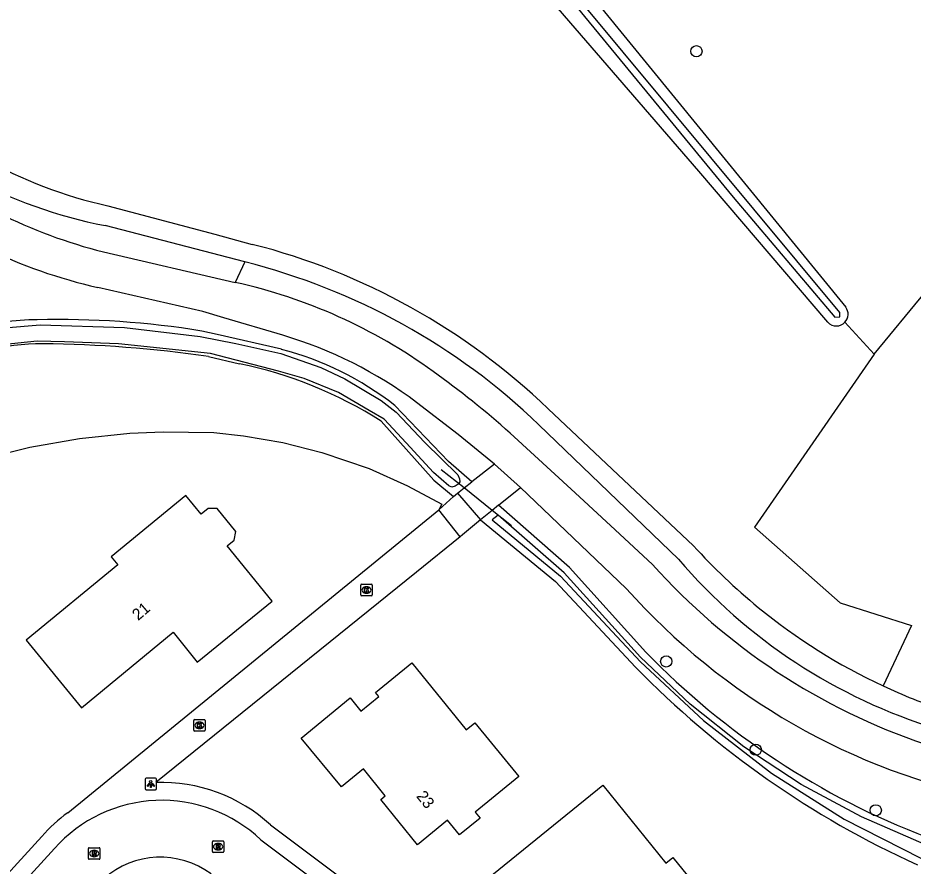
# Model space of a CAD drawing. Extents: x 159628 to 160723, y 388176 to 389416.
# Drawn here: x 160106.4 to 160184.1, y 388841.4 to 388915 of the extents above; entities that cross this region are included whole.
import ezdxf

# ---------------------------------------------------------------- set-up
doc = ezdxf.new("R2010")
doc.units = 0
for name, color, linetype in [('IMGEO_Berm_groen', 7, 'Continuous'), ('IMGEO_Boom', 7, 'Continuous'), ('IMGEO_Duiker', 7, 'Continuous'), ('IMGEO_Erf', 7, 'Continuous'), ('IMGEO_Fietspad_gesloten', 7, 'Continuous'), ('IMGEO_Grasland_agrarisch', 7, 'Continuous'), ('IMGEO_Grasland_overig', 7, 'Continuous'), ('IMGEO_Kolk', 7, 'Continuous'), ('IMGEO_Lichtpunt', 7, 'Continuous'), ('IMGEO_Loofbos', 7, 'Continuous'), ('IMGEO_Muur', 7, 'Continuous'), ('IMGEO_Pand', 7, 'Continuous'), ('IMGEO_Pand_nummerreeks', 7, 'Continuous'), ('IMGEO_Rijbaan_lokaal_open', 7, 'Continuous'), ('IMGEO_Rioolput', 7, 'Continuous'), ('IMGEO_Voetpad_open', 7, 'Continuous'), ('IMGEO_Waterloop', 7, 'Continuous')]:
    doc.layers.add(name, color=color, linetype=linetype)

msp = doc.modelspace()

# ---------------------------------------------------------------- linework, layer by layer
at = {"layer": 'IMGEO_Berm_groen'}
for points in [[(160126.079, 388893.808), (160125.223, 388892.036)], [(160160.876, 388859.965), (160154.236, 388867.293), (160148.075, 388872.699)]]:
    msp.add_lwpolyline(points, dxfattribs=at)
msp.add_arc((160209.329, 388907.014), 67.537, 224.15722, 249.1234, dxfattribs=at)
at = {"layer": 'IMGEO_Boom'}
for centre in [(160165.267, 388912.086), (160162.647, 388859.156), (160170.41, 388851.499), (160180.828, 388846.239)]:
    msp.add_circle(centre, 0.489, dxfattribs=at)
at = {"layer": 'IMGEO_Duiker'}
msp.add_lwpolyline([(160149.214, 388870.917), (160147.533, 388872.261), (160145.099, 388874.206), (160143.12, 388875.788)], dxfattribs=at)
at = {"layer": 'IMGEO_Erf'}
msp.add_lwpolyline([(160146.523, 388871.443), (160153.027, 388866.078), (160159.969, 388858.667)], dxfattribs=at)
msp.add_arc((160217.806, 388915.151), 80.842, 224.32195, 245.63246, dxfattribs=at)
at = {"layer": 'IMGEO_Fietspad_gesloten'}
for points in [[(160113.801, 388894.677), (160125.223, 388892.036)], [(160129.373, 388887.452), (160124.242, 388888.964), (160122.442, 388889.495), (160113.319, 388891.599)], [(160147.737, 388876.259), (160144.602, 388878.841), (160140.983, 388881.624)], [(160149.101, 388878.958), (160154.74, 388873.784), (160158.211, 388870.565), (160161.453, 388867.574)], [(160149.983, 388874.244), (160147.737, 388876.259)], [(160159.177, 388865.484), (160149.983, 388874.244)]]:
    msp.add_lwpolyline(points, dxfattribs=at)
for centre, radius, start, end in [((160124.753, 388938.066), 44.75, 230.95322, 255.83428), ((160123.158, 388935.319), 44.814, 230.80433, 257.31731), ((160115.19, 388846.727), 46.406, 54.08271, 77.51447), ((160118.674, 388851.661), 37.356, 53.33086, 73.35758), ((160096.478, 388820.054), 78.987, 48.22355, 54.44012), ((160202.862, 388904.655), 55.585, 221.84443, 251.40851), ((160202.564, 388904.147), 58.114, 221.70465, 258.72122)]:
    msp.add_arc(centre, radius, start, end, dxfattribs=at)
at = {"layer": 'IMGEO_Grasland_agrarisch'}
for points in [[(160152.521, 388921.233), (160157.028, 388915.832), (160178.23, 388889.88)], [(160176.67, 388888.573), (160165.48, 388901.685), (160150.482, 388919.031), (160150.332, 388919.393)], [(160178.159, 388888.584), (160180.698, 388885.821)]]:
    msp.add_lwpolyline(points, dxfattribs=at)
for centre, start, end in [((160177.412, 388889.275), 317.23027, 36.49822), ((160177.409, 388889.271), 223.37071, 317.47582)]:
    msp.add_arc(centre, 1.017, start, end, dxfattribs=at)
at = {"layer": 'IMGEO_Grasland_overig'}
for points in [[(160129.253, 388886.228), (160123.678, 388887.511), (160122.355, 388887.816)], [(160145.765, 388874.725), (160143.753, 388876.491), (160139.079, 388881.366)]]:
    msp.add_lwpolyline(points, dxfattribs=at)
for centre, radius, start, end in [((160108.302, 388865.871), 22.924, 90.59566, 105.3732), ((160109.91, 388810.873), 77.943, 80.81269, 91.35748), ((160122.371, 388859.96), 27.154, 52.02728, 75.31942)]:
    msp.add_arc(centre, radius, start, end, dxfattribs=at)
at = {"layer": 'IMGEO_Kolk'}
for p, q in [((160136.131, 388864.922), (160136.131, 388865.774)), ((160136.206, 388865.848), (160137.058, 388865.848)), ((160137.132, 388865.774), (160137.132, 388864.922)), ((160136.642, 388865.068), (160136.617, 388865.068)), ((160136.619, 388865.628), (160136.644, 388865.628)), ((160137.058, 388864.848), (160136.206, 388864.848)), ((160121.637, 388853.186), (160121.637, 388854.038)), ((160121.712, 388854.112), (160122.564, 388854.112)), ((160122.638, 388854.038), (160122.638, 388853.186)), ((160122.148, 388853.332), (160122.123, 388853.332)), ((160122.125, 388853.892), (160122.15, 388853.892)), ((160122.564, 388853.112), (160121.712, 388853.112))]:
    msp.add_line(p, q, dxfattribs=at)
for points in [[(160136.131, 388864.922), (160136.131, 388865.774)], [(160136.206, 388865.848), (160137.058, 388865.848)], [(160137.132, 388865.774), (160137.132, 388864.922)], [(160136.452, 388865.548), (160136.575, 388865.548), (160136.575, 388865.397), (160136.705, 388865.548), (160136.869, 388865.548), (160136.723, 388865.397), (160136.876, 388865.148), (160136.724, 388865.148), (160136.639, 388865.312), (160136.575, 388865.245), (160136.575, 388865.148), (160136.452, 388865.148), (160136.452, 388865.548)], [(160137.058, 388864.848), (160136.206, 388864.848)], [(160121.637, 388853.186), (160121.637, 388854.038)], [(160121.712, 388854.112), (160122.564, 388854.112)], [(160122.638, 388854.038), (160122.638, 388853.186)], [(160121.958, 388853.812), (160122.081, 388853.812), (160122.081, 388853.661), (160122.211, 388853.812), (160122.375, 388853.812), (160122.229, 388853.661), (160122.382, 388853.412), (160122.23, 388853.412), (160122.145, 388853.576), (160122.081, 388853.509), (160122.081, 388853.412), (160121.958, 388853.412), (160121.958, 388853.812)], [(160122.564, 388853.112), (160121.712, 388853.112)]]:
    msp.add_lwpolyline(points, dxfattribs=at)
for centre, start, end in [((160136.208, 388865.772), 91.55205, 178.44795), ((160136.208, 388865.772), 91.55205, 178.44795), ((160137.056, 388865.772), 1.55205, 88.44795), ((160137.056, 388865.772), 1.55205, 88.44795), ((160136.208, 388864.924), 181.55205, 268.44795), ((160136.208, 388864.924), 181.55205, 268.44795), ((160137.056, 388864.924), 271.55205, 358.44795), ((160137.056, 388864.924), 271.55205, 358.44795), ((160121.714, 388854.036), 91.55205, 178.44795), ((160121.714, 388854.036), 91.55205, 178.44795), ((160122.562, 388854.036), 1.55205, 88.44795), ((160122.562, 388854.036), 1.55205, 88.44795), ((160121.714, 388853.188), 181.55205, 268.44795), ((160121.714, 388853.188), 181.55205, 268.44795), ((160122.562, 388853.188), 271.55205, 358.44795), ((160122.562, 388853.188), 271.55205, 358.44795)]:
    msp.add_arc(centre, 0.0765, start, end, dxfattribs=at)
for centre, major_axis, ratio, start_param, end_param in [((160136.618, 388865.348), (-0.387, 0.002), 0.722429, 4.712389, 7.853982), ((160136.643, 388865.348), (-0.39, 0.002), 0.717154, 1.570796, 4.712389), ((160122.124, 388853.612), (-0.387, 0.002), 0.722429, 4.712389, 7.853982), ((160122.149, 388853.612), (-0.39, 0.002), 0.717154, 1.570796, 4.712389)]:
    msp.add_ellipse(centre, major_axis=major_axis, ratio=ratio, start_param=start_param, end_param=end_param, dxfattribs=at)
at = {"layer": 'IMGEO_Lichtpunt'}
for p, q in [((160117.414, 388848.929), (160117.414, 388848.122)), ((160117.414, 388848.929), (160117.414, 388848.122)), ((160118.316, 388849.024), (160117.508, 388849.024)), ((160118.316, 388849.024), (160117.508, 388849.024)), ((160118.41, 388848.122), (160118.41, 388848.929)), ((160118.41, 388848.122), (160118.41, 388848.929)), ((160117.508, 388848.028), (160118.316, 388848.028)), ((160117.508, 388848.028), (160118.316, 388848.028))]:
    msp.add_line(p, q, dxfattribs=at)
for points in [[(160117.788, 388848.593), (160117.827, 388848.565), (160117.639, 388848.303), (160117.601, 388848.33), (160117.788, 388848.593)], [(160118, 388848.565), (160118.038, 388848.592), (160118.225, 388848.33), (160118.186, 388848.302), (160118, 388848.565)], [(160117.89, 388848.545), (160117.937, 388848.545), (160117.937, 388848.223), (160117.89, 388848.223), (160117.89, 388848.545)]]:
    msp.add_lwpolyline(points, dxfattribs=at)
msp.add_circle((160117.913, 388848.727), 0.0994, dxfattribs=at)
for centre, start, end in [((160117.508, 388848.929), 90, 180), ((160117.508, 388848.929), 90, 180), ((160118.316, 388848.929), 0, 90), ((160118.316, 388848.929), 0, 90), ((160117.508, 388848.122), 180, 270), ((160117.508, 388848.122), 180, 270), ((160118.316, 388848.122), 270, 0), ((160118.316, 388848.122), 270, 360)]:
    msp.add_arc(centre, 0.0946, start, end, dxfattribs=at)
at = {"layer": 'IMGEO_Loofbos'}
for points in [[(160180.698, 388885.821), (160198.615, 388907.555), (160207.1, 388917.768)], [(160122.932, 388885.596), (160125.623, 388884.972)], [(160180.698, 388885.821), (160170.293, 388870.81), (160177.732, 388864.231), (160183.942, 388862.28), (160181.458, 388857.036)], [(160137.913, 388879.986), (160142.476, 388874.889), (160144.18, 388873.466)], [(160014.595, 388792.981), (160022.506, 388802.773), (160031.91, 388812.426), (160037.244, 388817.834), (160050.01, 388832.209), (160076.202, 388860.613), (160088.475, 388870.635), (160091.325, 388872.058), (160096.312, 388874.263), (160100.4, 388875.818), (160103.183, 388876.691), (160107.426, 388877.75), (160111.735, 388878.505), (160116.086, 388878.95), (160119, 388879.074), (160123.373, 388879), (160125.963, 388878.728), (160129.384, 388878.138), (160132.751, 388877.291), (160136.853, 388875.88), (160140.197, 388874.392), (160143.174, 388872.785), (160142.904, 388872.292)]]:
    msp.add_lwpolyline(points, dxfattribs=at)
for centre, radius, start, end in [((160108.633, 388865.149), 21.555, 90.2422, 116.86422), ((160107.71, 388781.9), 104.807, 81.64893, 89.54514), ((160118.274, 388849.216), 36.503, 57.45088, 78.38476)]:
    msp.add_arc(centre, radius, start, end, dxfattribs=at)
at = {"layer": 'IMGEO_Muur'}
for points in [[(160144.771, 388869.961), (160140.979, 388866.903)], [(160144.974, 388870.125), (160144.771, 388869.961)], [(160140.979, 388866.903), (160118.345, 388848.647)]]:
    msp.add_lwpolyline(points, dxfattribs=at)
at = {"layer": 'IMGEO_Pand'}
for points in [[(160111.899, 388855.13), (160119.852, 388861.687), (160121.948, 388859.097), (160128.456, 388864.393), (160124.543, 388869.17), (160125.147, 388869.665), (160125.286, 388870.425), (160123.658, 388872.414), (160122.886, 388872.425), (160122.284, 388871.931), (160120.967, 388873.54), (160114.475, 388868.221), (160115.046, 388867.526), (160107.085, 388861.004), (160111.899, 388855.13)], [(160146.072, 388846.069), (160146.488, 388845.559), (160144.711, 388844.108), (160143.67, 388845.383), (160141.06, 388843.254), (160137.875, 388847.171), (160138.265, 388847.49), (160136.363, 388849.83), (160134.459, 388848.264), (160130.957, 388852.509), (160135.216, 388855.983), (160136.144, 388854.842), (160137.695, 388856.104), (160137.411, 388856.453), (160140.568, 388859.02), (160145.288, 388853.218), (160146.04, 388853.83), (160149.86, 388849.16), (160146.072, 388846.069)], [(160162.608, 388841.646), (160163.23, 388842.15), (160168.45, 388835.71), (160159.612, 388828.546), (160157.368, 388831.336), (160156.12, 388830.327), (160150.886, 388836.787), (160150.256, 388836.284), (160147.042, 388840.239), (160157.129, 388848.41), (160162.608, 388841.646)]]:
    msp.add_lwpolyline(points, dxfattribs=at)
at = {"layer": 'IMGEO_Rijbaan_lokaal_open'}
for points in [[(160127.462, 388843.684), (160157.474, 388821.21)], [(160070.436, 388800.085), (160109.545, 388842.928)]]:
    msp.add_lwpolyline(points, dxfattribs=at)
for centre, radius, start, end in [((160118.87, 388834.61), 12.496, 46.56442, 138.26786), ((160118.744, 388834.805), 7.369, 53.38393, 131.6797)]:
    msp.add_arc(centre, radius, start, end, dxfattribs=at)
at = {"layer": 'IMGEO_Rioolput'}
for p, q in [((160123.253, 388842.661), (160123.253, 388843.513)), ((160123.328, 388843.587), (160124.18, 388843.587)), ((160123.741, 388843.367), (160123.766, 388843.367)), ((160124.254, 388843.513), (160124.254, 388842.661)), ((160112.497, 388842.067), (160112.497, 388842.919)), ((160112.572, 388842.993), (160113.424, 388842.993)), ((160112.985, 388842.773), (160113.01, 388842.773)), ((160113.498, 388842.919), (160113.498, 388842.067)), ((160124.18, 388842.587), (160123.328, 388842.587)), ((160123.764, 388842.807), (160123.739, 388842.807)), ((160113.424, 388841.993), (160112.572, 388841.993)), ((160113.008, 388842.213), (160112.983, 388842.213))]:
    msp.add_line(p, q, dxfattribs=at)
for points in [[(160123.253, 388842.661), (160123.253, 388843.513)], [(160123.328, 388843.587), (160124.18, 388843.587)], [(160123.842, 388843.285), (160123.59, 388843.287), (160123.59, 388842.887)], [(160123.768, 388843.206), (160123.714, 388843.206), (160123.714, 388843.125)], [(160123.714, 388843.125), (160123.766, 388843.125)], [(160124.254, 388843.513), (160124.254, 388842.661)], [(160112.497, 388842.067), (160112.497, 388842.919)], [(160112.572, 388842.993), (160113.424, 388842.993)], [(160113.086, 388842.691), (160112.834, 388842.693), (160112.834, 388842.293)], [(160112.834, 388842.293), (160112.958, 388842.293), (160112.958, 388842.455), (160112.969, 388842.455)], [(160113.012, 388842.612), (160112.958, 388842.612), (160112.958, 388842.531)], [(160112.958, 388842.531), (160113.01, 388842.531)], [(160113.016, 388842.426), (160113.087, 388842.293), (160113.227, 388842.293), (160113.162, 388842.419)], [(160113.498, 388842.919), (160113.498, 388842.067)], [(160124.18, 388842.587), (160123.328, 388842.587)], [(160123.59, 388842.887), (160123.714, 388842.887), (160123.714, 388843.049), (160123.725, 388843.049)], [(160123.772, 388843.02), (160123.843, 388842.887), (160123.983, 388842.887), (160123.918, 388843.013)], [(160113.424, 388841.993), (160112.572, 388841.993)]]:
    msp.add_lwpolyline(points, dxfattribs=at)
for centre, radius, start, end in [((160123.33, 388843.511), 0.0765, 91.55205, 178.44795), ((160123.33, 388843.511), 0.0765, 91.55205, 178.44795), ((160123.75, 388843.314), 0.19, 274.7715, 282.96867), ((160123.774, 388843.11), 0.0964, 77.00612, 93.18647), ((160123.788, 388843.167), 0.0378, 276.66336, 79.67722), ((160123.841, 388843.175), 0.109, 350.36119, 89.41601), ((160123.839, 388843.175), 0.112, 277.58423, 350.98172), ((160124.178, 388843.511), 0.0765, 1.55205, 88.44795), ((160124.178, 388843.511), 0.0765, 1.55205, 88.44795), ((160112.574, 388842.917), 0.0765, 91.55205, 178.44795), ((160112.574, 388842.917), 0.0765, 91.55205, 178.44795), ((160112.968, 388842.402), 0.0533, 26.02933, 88.69889), ((160112.994, 388842.72), 0.19, 274.7715, 282.96867), ((160113.018, 388842.516), 0.0964, 77.00612, 93.18647), ((160113.032, 388842.573), 0.0378, 276.66336, 79.67722), ((160113.085, 388842.581), 0.109, 350.36119, 89.41601), ((160113.083, 388842.581), 0.112, 277.58423, 350.98172), ((160113.067, 388842.366), 0.108, 29.51342, 73.79051), ((160113.422, 388842.917), 0.0765, 1.55205, 88.44795), ((160113.422, 388842.917), 0.0765, 1.55205, 88.44795), ((160123.33, 388842.663), 0.0765, 181.55205, 268.44795), ((160123.33, 388842.663), 0.0765, 181.55205, 268.44795), ((160123.724, 388842.996), 0.0533, 26.02933, 88.69889), ((160123.823, 388842.96), 0.108, 29.51342, 73.79051), ((160124.178, 388842.663), 0.0765, 271.55205, 358.44795), ((160124.178, 388842.663), 0.0765, 271.55205, 358.44795), ((160112.574, 388842.069), 0.0765, 181.55205, 268.44795), ((160112.574, 388842.069), 0.0765, 181.55205, 268.44795), ((160113.422, 388842.069), 0.0765, 271.55205, 358.44795), ((160113.422, 388842.069), 0.0765, 271.55205, 358.44795)]:
    msp.add_arc(centre, radius, start, end, dxfattribs=at)
for centre, major_axis, ratio, start_param, end_param in [((160123.74, 388843.087), (-0.387, 0.002), 0.722429, 4.712389, 7.853982), ((160123.765, 388843.087), (-0.39, 0.002), 0.717154, 1.570796, 4.712389), ((160112.984, 388842.493), (-0.387, 0.002), 0.722429, 4.712389, 7.853982), ((160113.009, 388842.493), (-0.39, 0.002), 0.717154, 1.570796, 4.712389)]:
    msp.add_ellipse(centre, major_axis=major_axis, ratio=ratio, start_param=start_param, end_param=end_param, dxfattribs=at)
at = {"layer": 'IMGEO_Voetpad_open'}
for points in [[(160147.737, 388876.259), (160145.765, 388874.725)], [(160144.53, 388873.764), (160145.099, 388874.206), (160145.765, 388874.725)], [(160148.075, 388872.699), (160149.983, 388874.244)], [(160142.904, 388872.292), (160144.18, 388873.466)], [(160144.18, 388873.466), (160144.53, 388873.764)], [(160144.53, 388873.764), (160146.523, 388871.443)], [(160148.075, 388872.699), (160147.533, 388872.261), (160146.523, 388871.443)], [(160110.715, 388846.034), (160142.904, 388872.292)], [(160144.771, 388869.961), (160142.904, 388872.292)], [(160146.523, 388871.443), (160144.974, 388870.125), (160144.771, 388869.961)], [(160144.771, 388869.961), (160140.979, 388866.903), (160118.345, 388848.647)], [(160128.304, 388844.967), (160160.996, 388820.473)], [(160069.293, 388801.1), (160108.445, 388843.974)]]:
    msp.add_lwpolyline(points, dxfattribs=at)
for centre, radius, start, end in [((160118.861, 388834.727), 13.93, 47.31811, 92.12183), ((160119, 388834.624), 14.101, 125.98323, 138.46357)]:
    msp.add_arc(centre, radius, start, end, dxfattribs=at)
at = {"layer": 'IMGEO_Waterloop'}
for points in [[(160076.321, 389013.252), (160075.983, 389013.295), (160075.73, 389013.175), (160075.543, 389013.015), (160075.556, 389012.759), (160080.031, 389007.531), (160090.832, 388994.245), (160104.179, 388977.798), (160115.883, 388963.404), (160126.314, 388950.775), (160140.236, 388933.876), (160152.207, 388919.215), (160168.452, 388899.417), (160177.289, 388889.02), (160177.7, 388889.05), (160177.7, 388889.42), (160143.969, 388929.954), (160123.185, 388955.547), (160095.452, 388989.564), (160076.321, 389013.252)], [(160114.193, 388898.674), (160123.46, 388896.204), (160126.72, 388895.335)], [(160126.079, 388893.808), (160113.943, 388896.97)], [(160105.218, 388888.103), (160108.315, 388888.346), (160115.641, 388888.116), (160122.208, 388887.345), (160125.287, 388886.733), (160129.209, 388885.868), (160132.665, 388884.647), (160134.748, 388883.675), (160137.918, 388881.775), (160139.216, 388880.789), (160141.708, 388878.149), (160144.568, 388875.331), (160144.711, 388874.993), (160144.72, 388874.74), (160144.576, 388874.545), (160144.313, 388874.366), (160144.043, 388874.272), (160143.787, 388874.38), (160142.438, 388875.539), (160140.088, 388878.119), (160138.157, 388880.173), (160136.856, 388880.932), (160134.212, 388882.469), (160131.232, 388883.708), (160129.006, 388884.33), (160123.087, 388885.862), (160115.121, 388886.698), (160110.433, 388886.886), (160108.039, 388886.927), (160104.979, 388886.631)], [(160152.399, 388881.059), (160165.008, 388869.192)], [(160163.707, 388868.031), (160151.599, 388879.686)], [(160185.232, 388843.225), (160179.581, 388845.667), (160174.354, 388848.489), (160169.393, 388851.755), (160164.735, 388855.441), (160160.418, 388859.516), (160153.786, 388866.835), (160148.048, 388871.849), (160147.536, 388871.438), (160153.467, 388866.546), (160160.422, 388859.121), (160165.879, 388854.03), (160171.778, 388849.473), (160178.075, 388845.483), (160184.732, 388842.086)]]:
    msp.add_lwpolyline(points, dxfattribs=at)
for centre, radius, start, end in [((160122.797, 388937.487), 39.756, 223.95157, 257.50076), ((160121.787, 388937.668), 41.447, 224.20487, 259.09023), ((160112.454, 388839.44), 57.687, 46.17538, 75.6817), ((160112.163, 388838.541), 56.992, 46.21524, 75.86712), ((160203.298, 388903.791), 51.606, 222.10156, 230.73553), ((160200.172, 388899.158), 47.944, 220.48462, 253.0053), ((160203.283, 388903.781), 51.589, 230.74111, 244.97252), ((160203.286, 388903.781), 51.59, 244.96916, 251.29343)]:
    msp.add_arc(centre, radius, start, end, dxfattribs=at)

# ---------------------------------------------------------------- texts
at = {"layer": 'IMGEO_Pand_nummerreeks'}
for s, rotation, p in [('21', 40.54639, (160116.817, 388862.654)), ('23', 309.11533, (160140.902, 388847.444))]:
    msp.add_text(s, height=1, rotation=rotation, dxfattribs=at).set_placement(p)

doc.saveas('drawing.dxf')
